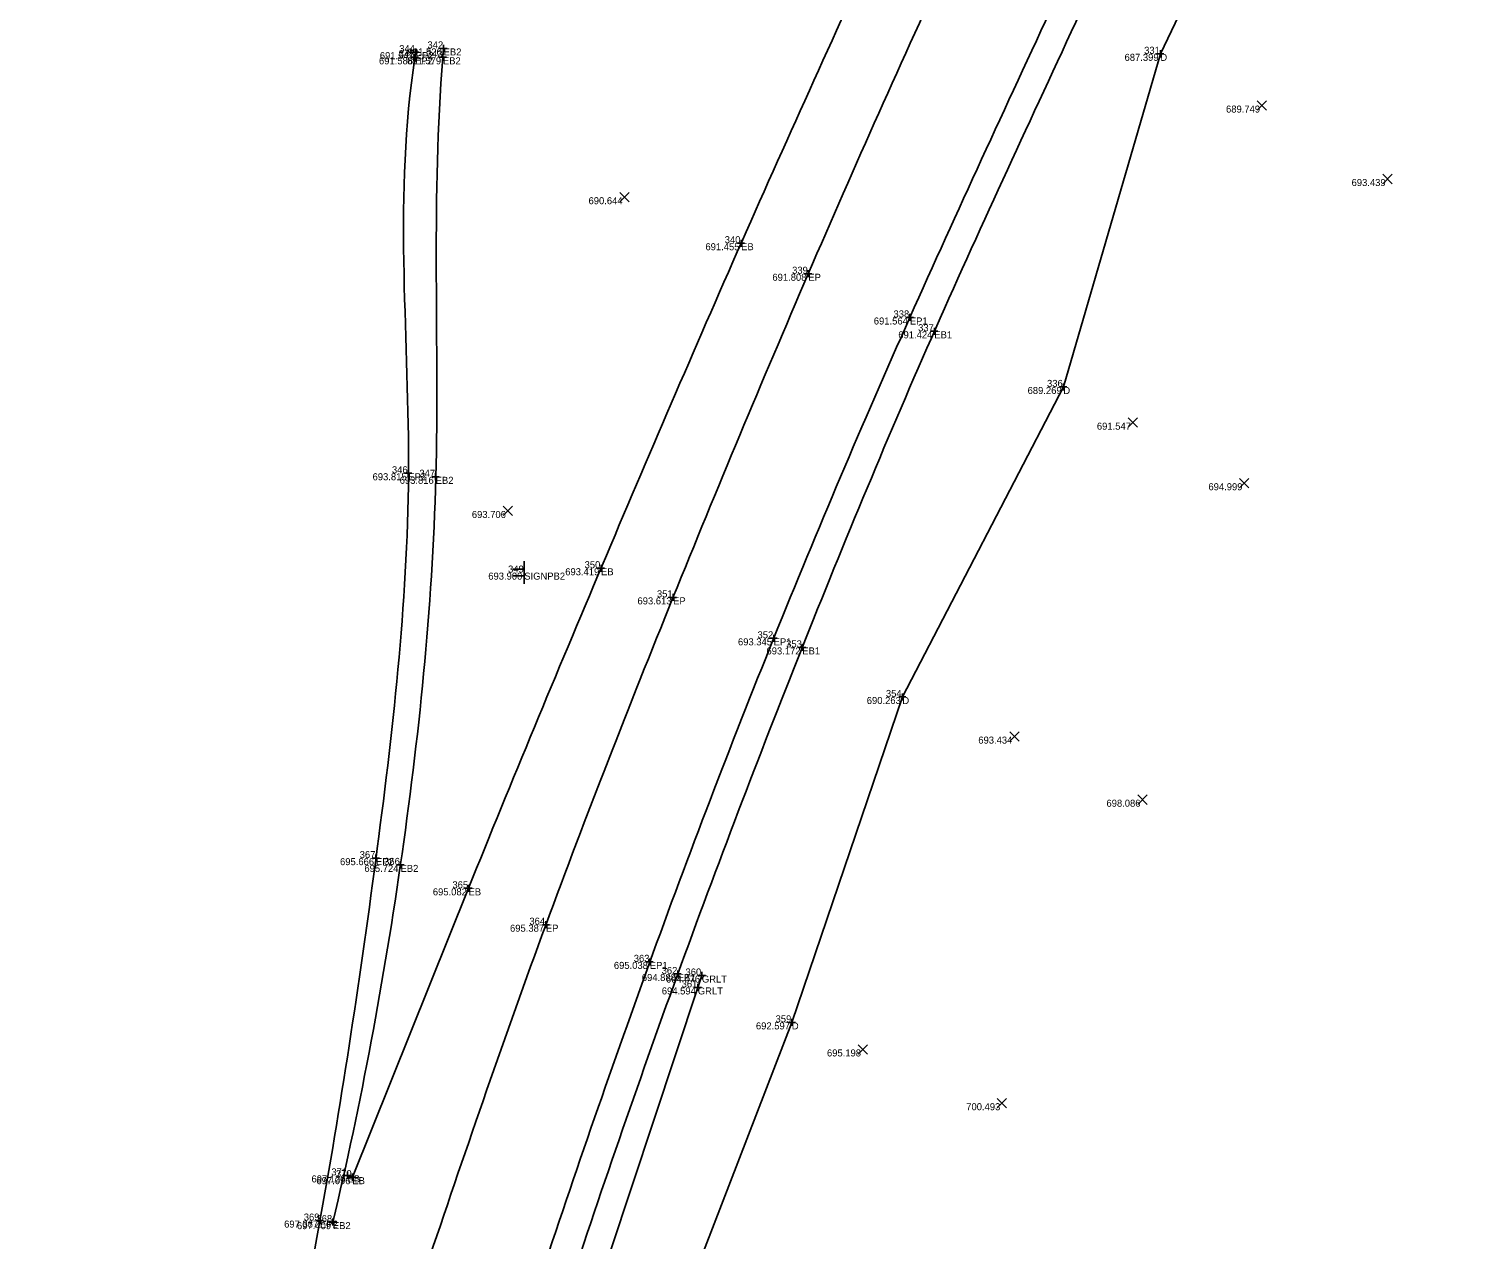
# Model space of a CAD drawing. Extents: x 2197382 to 2204062, y 634117 to 636522.
# Drawn here: x 2201922.4 to 2202128.8, y 634290.4 to 634462.4 of the extents above; entities that cross this region are included whole.
import ezdxf

# ---------------------------------------------------------------- set-up
doc = ezdxf.new("R2010")
doc.units = 0
for name, color, linetype in [('_CIVIL_CONSTRUCTION', 7, 'Continuous'), ('DR_X_Ditch', 7, 'Continuous'), ('GE_P_Alignment_100_Distances', 7, 'Continuous'), ('GE_P_Alignment_100_Stations', 7, 'Continuous'), ('GE_X_Alignment', 7, 'Continuous'), ('PF_X_Ground_Line', 7, 'Continuous'), ('RW_X_CL_100_Curve_Data', 7, 'Continuous'), ('SH_Border', 7, 'Continuous'), ('SH_Cut_Line', 7, 'Continuous'), ('SH_Data', 7, 'Continuous')]:
    doc.layers.add(name, color=color, linetype=linetype)

msp = doc.modelspace()

# ---------------------------------------------------------------- linework, layer by layer
at = {"layer": '_CIVIL_CONSTRUCTION'}
for p, q in [((2201981.25, 634460.17), (2201981.25, 634459.17)), ((2201976.67, 634458.41), (2201977.67, 634458.41)), ((2201976.79, 634459.14), (2201977.79, 634459.14)), ((2201977.17, 634458.91), (2201977.17, 634457.91)), ((2201977.17, 634458.41), (2201977.17, 634458.41)), ((2201977.29, 634459.64), (2201977.29, 634458.64)), ((2201977.29, 634459.14), (2201977.29, 634459.14)), ((2201980.65, 634458.41), (2201981.65, 634458.41)), ((2201980.75, 634459.67), (2201981.75, 634459.67)), ((2201981.15, 634458.91), (2201981.15, 634457.91)), ((2201981.15, 634458.41), (2201981.15, 634458.41)), ((2201981.25, 634459.67), (2201981.25, 634459.67)), ((2202082.54, 634458.9), (2202083.54, 634458.9)), ((2202083.04, 634459.4), (2202083.04, 634458.4)), ((2202083.04, 634458.9), (2202083.04, 634458.9)), ((2202023, 634431.99), (2202024, 634431.99)), ((2202023.5, 634432.49), (2202023.5, 634431.49)), ((2202023.5, 634431.99), (2202023.5, 634431.99)), ((2202032.54, 634427.65), (2202033.54, 634427.65)), ((2202033.04, 634428.15), (2202033.04, 634427.15)), ((2202033.04, 634427.65), (2202033.04, 634427.65)), ((2202046.96, 634421.44), (2202047.96, 634421.44)), ((2202047.46, 634421.94), (2202047.46, 634420.94)), ((2202047.46, 634421.44), (2202047.46, 634421.44)), ((2202050.44, 634419.48), (2202051.44, 634419.48)), ((2202050.94, 634419.98), (2202050.94, 634418.98)), ((2202050.94, 634419.48), (2202050.94, 634419.48)), ((2202068.76, 634411.57), (2202069.76, 634411.57)), ((2202069.26, 634412.07), (2202069.26, 634411.07)), ((2202069.26, 634411.57), (2202069.26, 634411.57)), ((2201975.73, 634399.3), (2201976.73, 634399.3)), ((2201976.23, 634399.8), (2201976.23, 634398.8)), ((2201976.23, 634399.3), (2201976.23, 634399.3)), ((2201979.62, 634398.8), (2201980.62, 634398.8)), ((2201980.12, 634399.3), (2201980.12, 634398.3)), ((2201980.12, 634398.8), (2201980.12, 634398.8)), ((2202003.1, 634385.81), (2202004.1, 634385.81)), ((2202003.6, 634386.31), (2202003.6, 634385.31)), ((2202003.6, 634385.81), (2202003.6, 634385.81)), ((2202013.34, 634381.67), (2202014.34, 634381.67)), ((2202013.84, 634382.17), (2202013.84, 634381.17)), ((2202013.84, 634381.67), (2202013.84, 634381.67)), ((2202027.62, 634375.85), (2202028.62, 634375.85)), ((2202028.12, 634376.35), (2202028.12, 634375.35)), ((2202028.12, 634375.85), (2202028.12, 634375.85)), ((2202031.68, 634374.56), (2202032.68, 634374.56)), ((2202032.18, 634375.06), (2202032.18, 634374.06)), ((2202032.18, 634374.56), (2202032.18, 634374.56)), ((2202045.9, 634367.52), (2202046.9, 634367.52)), ((2202046.4, 634368.02), (2202046.4, 634367.02)), ((2202046.4, 634367.52), (2202046.4, 634367.52)), ((2201971.14, 634344.62), (2201972.14, 634344.62)), ((2201971.64, 634345.12), (2201971.64, 634344.12)), ((2201971.64, 634344.62), (2201971.64, 634344.62)), ((2201974.63, 634343.66), (2201975.63, 634343.66)), ((2201975.13, 634344.16), (2201975.13, 634343.16)), ((2201975.13, 634343.66), (2201975.13, 634343.66)), ((2201984.79, 634340.83), (2201984.79, 634339.83)), ((2201984.29, 634340.33), (2201985.29, 634340.33)), ((2201984.79, 634340.33), (2201984.79, 634340.33)), ((2201995.27, 634335.16), (2201996.27, 634335.16)), ((2201995.77, 634335.66), (2201995.77, 634334.66)), ((2201995.77, 634335.16), (2201995.77, 634335.16)), ((2202010.53, 634330.38), (2202010.53, 634329.38)), ((2202010.03, 634329.88), (2202011.03, 634329.88)), ((2202010.53, 634329.88), (2202010.53, 634329.88)), ((2202014, 634328.16), (2202015, 634328.16)), ((2202014.5, 634328.66), (2202014.5, 634327.66)), ((2202014.5, 634328.16), (2202014.5, 634328.16)), ((2202017.93, 634328.44), (2202017.93, 634327.44)), ((2202016.85, 634326.25), (2202017.85, 634326.25)), ((2202017.35, 634326.75), (2202017.35, 634325.75)), ((2202017.35, 634326.25), (2202017.35, 634326.25)), ((2202017.43, 634327.94), (2202018.43, 634327.94)), ((2202017.93, 634327.94), (2202017.93, 634327.94)), ((2202030.7, 634321.78), (2202030.7, 634320.78)), ((2202030.2, 634321.28), (2202031.2, 634321.28)), ((2202030.7, 634321.28), (2202030.7, 634321.28)), ((2201967.1, 634299.54), (2201968.1, 634299.54)), ((2201967.6, 634300.04), (2201967.6, 634299.04)), ((2201967.6, 634299.54), (2201967.6, 634299.54)), ((2201967.79, 634299.29), (2201968.79, 634299.29)), ((2201968.29, 634299.79), (2201968.29, 634298.79)), ((2201968.29, 634299.29), (2201968.29, 634299.29)), ((2201963.2, 634293.12), (2201964.2, 634293.12)), ((2201963.7, 634293.62), (2201963.7, 634292.62)), ((2201963.7, 634293.12), (2201963.7, 634293.12)), ((2201965.02, 634292.9), (2201966.02, 634292.9)), ((2201965.52, 634293.4), (2201965.52, 634292.4)), ((2201965.52, 634292.9), (2201965.52, 634292.9))]:
    msp.add_line(p, q, dxfattribs=at)
at = {"layer": 'DR_X_Ditch'}
msp.add_lwpolyline([(2202157.96, 634604.45), (2202148.75, 634589.47), (2202127.84, 634547.21), (2202104.93, 634504.72), (2202083.04, 634458.9), (2202069.26, 634411.57), (2202046.4, 634367.52), (2202030.7, 634321.28), (2202012.02, 634272.77), (2201996.99, 634227.77), (2201983.35, 634180.78), (2201972.72, 634154.31)], dxfattribs=at)
at = {"layer": 'GE_P_Alignment_100_Distances'}
msp.add_line((2201977.29, 634459.14), (2201977.17, 634458.41), dxfattribs=at)
for points in [[(2202514.19, 635120), (2202501.95, 635108.79), (2202477.63, 635085.87), (2202443.41, 635049.36), (2202409.55, 635012.34), (2202376.26, 634974.99), (2202344.34, 634936.42), (2202312.72, 634897.79), (2202282.43, 634858.12), (2202252.58, 634818.18), (2202223.74, 634777.45), (2202196.69, 634735.5), (2202169.8, 634693.41), (2202144.64, 634650.36), (2202119.18, 634607.44), (2202097.03, 634562.79), (2202074.71, 634518.18), (2202053.15, 634473.28), (2202032.85, 634427.72), (2202013.67, 634381.72), (2201995.41, 634335.21), (2201979.19, 634288.02), (2201963.55, 634240.68), (2201953.92, 634208.98), (2201949.13, 634193.1)], [(2202525.02, 635108.11), (2202513.04, 635097.11), (2202489.33, 635074.07), (2202455.07, 635038.62), (2202421.29, 635002.1), (2202388.81, 634964.35), (2202356.35, 634926.75), (2202325.87, 634887.43), (2202295, 634848.95), (2202265.53, 634808.92), (2202237.35, 634768.89), (2202211.52, 634726.54), (2202183.6, 634685.47), (2202158.14, 634642.34), (2202133.69, 634599.43), (2202111.05, 634555.42), (2202088.76, 634511.33), (2202068.04, 634466.33), (2202047.21, 634421.56), (2202027.88, 634376.06), (2202010.16, 634329.7), (2201994.09, 634282.81), (2201978.74, 634235.43), (2201968.75, 634203.87), (2201963.85, 634187.95)], [(2201977.17, 634458.41), (2201974.18, 634438.92), (2201978.36, 634400.6), (2201972.08, 634345.48), (2201964.26, 634293.48), (2201953.85, 634243.8), (2201942.48, 634194.98), (2201931.83, 634153.17), (2201924.97, 634127.38), (2201922.38, 634117.79)]]:
    msp.add_open_spline(points, degree=3, dxfattribs=at)
at = {"layer": 'GE_P_Alignment_100_Stations'}
for p, q in [((2201992.7, 634386.79), (2201992.7, 634383.59)), ((2201992.7, 634385.67), (2201991.1, 634385.67)), ((2201992.7, 634384.71), (2201991.1, 634384.71)), ((2201992.7, 634385.19), (2201992.7, 634385.19))]:
    msp.add_line(p, q, dxfattribs=at)
at = {"layer": 'GE_X_Alignment'}
for p, q in [((2201981.25, 634459.67), (2201981.15, 634458.41)), ((2201984.79, 634340.33), (2201968.29, 634299.29)), ((2201968.29, 634299.29), (2201967.6, 634299.54))]:
    msp.add_line(p, q, dxfattribs=at)
for points in [[(2202540.06, 635152.93), (2202529.43, 635144.25), (2202507.23, 635123.46), (2202471.72, 635092.05), (2202435.62, 635056.76), (2202402.1, 635018.87), (2202368.73, 634981.48), (2202336.15, 634943.25), (2202304.62, 634904.21), (2202274.11, 634864.33), (2202244.37, 634823.83), (2202215.65, 634782.83), (2202187.65, 634741.05), (2202161.54, 634698.56), (2202134.84, 634656), (2202111.41, 634611.66), (2202087.71, 634567.52), (2202064.97, 634523.35), (2202044.2, 634477.97), (2202023.42, 634432.25), (2202003.66, 634386.18), (2201990.91, 634355.55), (2201984.79, 634340.33)], [(2202570.92, 635145.14), (2202556.1, 635132.41), (2202530.6, 635107.02), (2202492.19, 635071.28), (2202457.98, 635035.82), (2202424.73, 634999.38), (2202391.64, 634962.22), (2202359.56, 634924.46), (2202328.32, 634885.6), (2202298.37, 634846.53), (2202268.85, 634806.21), (2202240.94, 634765.59), (2202212.91, 634724.71), (2202187.2, 634682.69), (2202161.14, 634640.35), (2202137.99, 634596.95), (2202114.64, 634553.56), (2202092.28, 634509.95), (2202071.73, 634464.7), (2202050.81, 634420.11), (2202031.84, 634374.34), (2202014.23, 634328.21), (2201997.98, 634281.03), (2201983.22, 634233.69), (2201972.74, 634202.38), (2201968.03, 634186.79)], [(2201981.15, 634458.41), (2201979.52, 634438.57), (2201981.66, 634400.19), (2201976.03, 634344.74), (2201969.52, 634309.71), (2201965.52, 634292.9)]]:
    msp.add_open_spline(points, degree=3, dxfattribs=at)
at = {"layer": 'PF_X_Ground_Line'}
msp.add_lwpolyline([(2202017.93, 634327.94), (2202017.35, 634326.25), (2202001.8, 634279.24), (2201985.31, 634232.09), (2201970.11, 634185.7), (2201958.98, 634150.06)], dxfattribs=at)
at = {"layer": 'RW_X_CL_100_Curve_Data'}
for p, q in [((2202096.78, 634450.89), (2202098.11, 634452.22)), ((2202096.78, 634452.22), (2202098.11, 634450.89)), ((2202114.61, 634440.44), (2202115.94, 634441.78)), ((2202114.61, 634441.78), (2202115.94, 634440.44)), ((2202006.28, 634437.87), (2202007.62, 634439.2)), ((2202006.28, 634439.2), (2202007.62, 634437.87)), ((2202078.45, 634405.83), (2202079.79, 634407.16)), ((2202078.45, 634407.16), (2202079.79, 634405.83)), ((2202094.28, 634397.22), (2202095.61, 634398.56)), ((2202094.28, 634398.56), (2202095.61, 634397.22)), ((2201989.69, 634393.28), (2201991.03, 634394.62)), ((2201989.69, 634394.62), (2201991.03, 634393.28)), ((2202061.64, 634361.22), (2202062.97, 634362.56)), ((2202061.64, 634362.56), (2202062.97, 634361.22)), ((2202079.82, 634352.26), (2202081.15, 634353.59)), ((2202079.82, 634353.59), (2202081.15, 634352.26)), ((2202040.13, 634316.77), (2202041.46, 634318.11)), ((2202040.13, 634318.11), (2202041.46, 634316.77)), ((2202059.87, 634309.13), (2202061.2, 634310.47)), ((2202059.87, 634310.47), (2202061.2, 634309.13))]:
    msp.add_line(p, q, dxfattribs=at)

# ---------------------------------------------------------------- texts
at = {"layer": 'SH_Border'}
for s, p in [('EP2', (2201977.17, 634457.41)), ('EP2', (2201977.29, 634458.14)), ('EB2', (2201981.15, 634457.41)), ('EB2', (2201981.25, 634458.67)), ('D', (2202083.04, 634457.9)), ('EB', (2202023.5, 634430.99)), ('EP', (2202033.04, 634426.65)), ('EP1', (2202047.46, 634420.44)), ('EB1', (2202050.94, 634418.48)), ('D', (2202069.26, 634410.57)), ('EP2', (2201976.23, 634398.31)), ('EB2', (2201980.12, 634397.8)), ('EB', (2202003.6, 634384.81)), ('SIGNPB2', (2201992.7, 634384.19)), ('EP', (2202013.84, 634380.67)), ('EP1', (2202028.12, 634374.85)), ('EB1', (2202032.18, 634373.56)), ('D', (2202046.4, 634366.52)), ('EP2', (2201971.64, 634343.62)), ('EB2', (2201975.13, 634342.66)), ('EB', (2201984.79, 634339.33)), ('EP', (2201995.77, 634334.16)), ('EP1', (2202010.53, 634328.88)), ('EB1', (2202014.5, 634327.16)), ('GRLT', (2202017.93, 634326.94)), ('GRLT', (2202017.35, 634325.25)), ('D', (2202030.7, 634320.28)), ('EB', (2201967.6, 634298.54)), ('EB', (2201968.29, 634298.29)), ('EP2', (2201963.7, 634292.12)), ('EB2', (2201965.52, 634291.9))]:
    msp.add_text(s, height=1, dxfattribs=at).set_placement(p)
at = {"layer": 'SH_Cut_Line'}
for s, p in [('344', (2201974.94, 634459.14)), ('342', (2201978.96, 634459.67)), ('345', (2201974.88, 634458.41)), ('343', (2201978.86, 634458.41)), ('331', (2202080.73, 634458.9)), ('340', (2202021.17, 634431.99)), ('339', (2202030.74, 634427.65)), ('338', (2202045.14, 634421.44)), ('337', (2202048.63, 634419.48)), ('336', (2202066.94, 634411.57)), ('346', (2201973.91, 634399.3)), ('347', (2201977.8, 634398.8)), ('349', (2201990.4, 634385.19)), ('350', (2202001.27, 634385.81)), ('351', (2202011.54, 634381.67)), ('352', (2202025.83, 634375.85)), ('353', (2202029.89, 634374.56)), ('354', (2202044.06, 634367.52)), ('367', (2201969.33, 634344.62)), ('366', (2201972.8, 634343.66)), ('365', (2201982.5, 634340.33)), ('364', (2201993.43, 634335.16)), ('363', (2202008.25, 634329.88)), ('362', (2202012.21, 634328.16)), ('360', (2202015.6, 634327.94)), ('361', (2202015.05, 634326.25)), ('359', (2202028.39, 634321.28)), ('371', (2201965.3, 634299.54)), ('370', (2201965.96, 634299.29)), ('369', (2201961.39, 634293.12)), ('368', (2201963.19, 634292.9))]:
    msp.add_text(s, height=1, dxfattribs=at).set_placement(p)
at = {"layer": 'SH_Data'}
for s, p in [('691.588', (2201972.07, 634457.41)), ('691.547', (2201972.19, 634458.14)), ('691.579', (2201976.06, 634457.41)), ('691.526', (2201976.15, 634458.67)), ('687.399', (2202077.95, 634457.9)), ('689.749', (2202092.36, 634450.55)), ('693.439', (2202110.19, 634440.11)), ('690.644', (2202001.83, 634437.53)), ('691.455', (2202018.43, 634430.99)), ('691.808', (2202027.94, 634426.65)), ('691.564', (2202042.34, 634420.44)), ('691.424', (2202045.82, 634418.48)), ('689.269', (2202064.18, 634410.57)), ('691.547', (2202074.02, 634405.49)), ('693.815', (2201971.16, 634398.31)), ('693.816', (2201975.01, 634397.8)), ('694.999', (2202089.86, 634396.89)), ('693.706', (2201985.26, 634392.95)), ('693.419', (2201998.52, 634384.81)), ('693.900', (2201987.59, 634384.19)), ('693.613', (2202008.78, 634380.67)), ('693.345', (2202023.05, 634374.85)), ('693.172', (2202027.1, 634373.56)), ('690.263', (2202041.34, 634366.52)), ('693.434', (2202057.18, 634360.89)), ('698.086', (2202075.38, 634351.92)), ('695.666', (2201966.54, 634343.62)), ('695.724', (2201970, 634342.66)), ('695.082', (2201979.72, 634339.33)), ('695.387', (2201990.68, 634334.16)), ('695.038', (2202005.43, 634328.88)), ('694.888', (2202009.4, 634327.16)), ('694.476', (2202012.83, 634326.94)), ('694.594', (2202012.23, 634325.25)), ('692.597', (2202025.6, 634320.28)), ('695.198', (2202035.69, 634316.44)), ('700.493', (2202055.47, 634308.8)), ('697.120', (2201962.49, 634298.54)), ('697.096', (2201963.19, 634298.29)), ('697.367', (2201958.6, 634292.12)), ('697.409', (2201960.43, 634291.9))]:
    msp.add_text(s, height=1, dxfattribs=at).set_placement(p)

doc.saveas('drawing.dxf')
